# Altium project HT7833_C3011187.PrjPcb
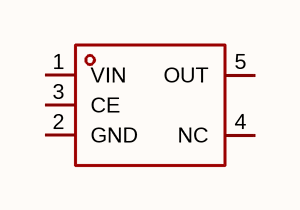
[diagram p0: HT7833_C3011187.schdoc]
1 sheet, 1 parts. Net scope: global (net labels, ports and power ports of the same name join across sheets).

## Sheet HT7833_C3011187.schdoc
size 127 x 101 mm

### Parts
U?  ht7833_c3011187  [SOT-23-5_L2.9-W1.6-P0.95-LS2.8-BL]  (value not drawn)

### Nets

Not connected (* = marked no-connect by the designer): U? 1(VIN) 2(GND) 3(CE) 4(NC) 5(OUT)

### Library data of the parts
U? = ht7833_c3011187: 输出极性:正极;工作电压:5.5V;输出电压:3.3V;输出电流:500mA;电源纹波抑制比(PSRR):80dB@(100Hz);输出类型:固定;; Manufacturer: TECH PUBLIC(台舟); ManufacturerPart: HT7833; AddInBom: yes; ModelId: 018c57e721114987ae90467fe9f1d259; ModelTransform: 114.96,110.236,0,0,0,0,0,0,0; Output Configuration: 正极; Voltage - Supply: 5.5V; Output Voltage: 3.3V; Output Current: 500mA; Voltage Dropout: 320mV@(500mA); standby current: 2uA; Output Type: 固定; Number of Outputs: 1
